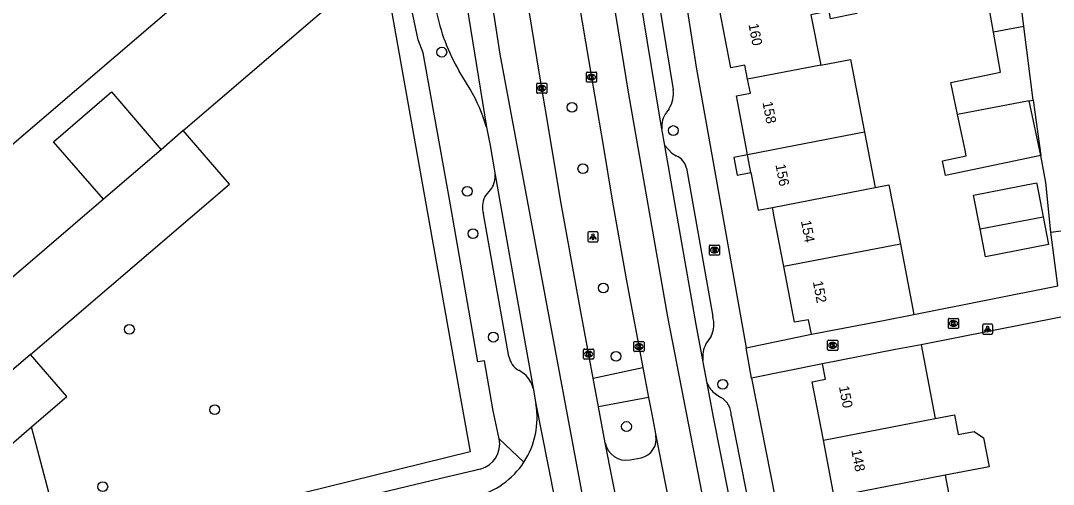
# Model space of a CAD drawing. Extents: x 158474 to 159560, y 388525 to 389605.
# Drawn here: x 159182.5 to 159285.1, y 388966.4 to 389012.4 of the extents above; entities that cross this region are included whole.
import ezdxf

# ---------------------------------------------------------------- set-up
doc = ezdxf.new("R2010")
doc.units = 0
for name, color, linetype in [('IMGEO_Boom', 7, 'Continuous'), ('IMGEO_Brandkraan', 7, 'Continuous'), ('IMGEO_Groenvoorziening', 7, 'Continuous'), ('IMGEO_Kolk', 7, 'Continuous'), ('IMGEO_Lichtpunt', 7, 'Continuous'), ('IMGEO_Muur', 7, 'Continuous'), ('IMGEO_Pand', 7, 'Continuous'), ('IMGEO_Pand_nummerreeks', 7, 'Continuous'), ('IMGEO_Parkeervlak_open', 7, 'Continuous'), ('IMGEO_Rijbaan_lokaal_gesloten', 7, 'Continuous'), ('IMGEO_Rijbaan_lokaal_open', 7, 'Continuous'), ('IMGEO_Voetpad_open', 7, 'Continuous')]:
    doc.layers.add(name, color=color, linetype=linetype)

msp = doc.modelspace()

# ---------------------------------------------------------------- linework, layer by layer
at = {"layer": 'IMGEO_Boom'}
for centre in [(159224.35, 389009.27), (159237.29, 389003.8), (159247.35, 389001.49), (159238.37, 388997.71), (159226.88, 388995.46), (159227.45, 388991.26), (159240.4, 388985.87), (159193.33, 388981.76), (159229.47, 388980.99), (159241.66, 388979.09), (159252.26, 388976.31), (159201.8, 388973.79), (159242.7, 388972.12), (159190.68, 388966.15)]:
    msp.add_circle(centre, 0.489, dxfattribs=at)
at = {"layer": 'IMGEO_Brandkraan'}
for p, q in [((159250.94, 388989.2), (159250.94, 388990.05)), ((159251.01, 388990.13), (159251.87, 388990.13)), ((159251.87, 388989.13), (159251.01, 388989.13)), ((159251.45, 388989.35), (159251.42, 388989.35)), ((159251.43, 388989.91), (159251.45, 388989.91)), ((159251.94, 388990.05), (159251.94, 388989.2))]:
    msp.add_line(p, q, dxfattribs=at)
for points in [[(159250.94, 388989.2), (159250.94, 388990.05)], [(159251.01, 388990.13), (159251.87, 388990.13)], [(159251.87, 388989.13), (159251.01, 388989.13)], [(159251.29, 388989.83), (159251.29, 388989.43), (159251.5, 388989.43)], [(159251.52, 388989.83), (159251.29, 388989.83)], [(159251.46, 388989.75), (159251.41, 388989.75), (159251.41, 388989.67)], [(159251.41, 388989.67), (159251.46, 388989.67)], [(159251.47, 388989.59), (159251.41, 388989.59), (159251.41, 388989.51)], [(159251.41, 388989.51), (159251.47, 388989.51)], [(159251.94, 388990.05), (159251.94, 388989.2)]]:
    msp.add_lwpolyline(points, dxfattribs=at)
for centre, radius, start, end in [((159251.01, 388990.05), 0.0765, 91.552, 178.448), ((159251.01, 388990.05), 0.0765, 91.552, 178.448), ((159251.01, 388989.2), 0.0765, 181.552, 268.448), ((159251.01, 388989.2), 0.0765, 181.552, 268.448), ((159251.47, 388989.71), 0.0379, 267.8285, 90.9355), ((159251.47, 388989.55), 0.0404, 269.8759, 90.5077), ((159251.5, 388989.68), 0.251, 268.6676, 293.5347), ((159251.52, 388989.68), 0.145, 59.4692, 91.5367), ((159251.55, 388989.73), 0.0922, 285.5137, 58.1501), ((159251.55, 388989.54), 0.105, 301.3115, 78.989), ((159251.86, 388990.05), 0.0765, 1.552, 88.448), ((159251.86, 388990.05), 0.0765, 1.552, 88.448), ((159251.86, 388989.2), 0.0765, 271.552, 358.448), ((159251.86, 388989.2), 0.0765, 271.552, 358.448)]:
    msp.add_arc(centre, radius, start, end, dxfattribs=at)
for centre, major_axis, ratio, start_param, end_param in [((159251.43, 388989.63), (-0.387, 0.002), 0.722429, 4.712389, 7.853982), ((159251.45, 388989.63), (-0.39, 0.002), 0.717154, 1.570796, 4.712389)]:
    msp.add_ellipse(centre, major_axis=major_axis, ratio=ratio, start_param=start_param, end_param=end_param, dxfattribs=at)
at = {"layer": 'IMGEO_Groenvoorziening'}
msp.add_lwpolyline([(159218.48, 389018.41), (159226.05, 388975.87), (159227.16, 388969.61), (159186.89, 388959.67), (159183.61, 388972.1)], dxfattribs=at)
at = {"layer": 'IMGEO_Kolk'}
for p, q in [((159238.72, 389006.37), (159238.72, 389007.22)), ((159238.8, 389007.29), (159239.65, 389007.29)), ((159239.21, 389007.07), (159239.24, 389007.07)), ((159239.72, 389007.22), (159239.72, 389006.37)), ((159233.78, 389005.27), (159233.78, 389006.12)), ((159233.85, 389006.19), (159234.71, 389006.19)), ((159234.27, 389005.97), (159234.29, 389005.97)), ((159234.78, 389006.12), (159234.78, 389005.27)), ((159239.65, 389006.29), (159238.8, 389006.29)), ((159239.23, 389006.51), (159239.21, 389006.51)), ((159234.71, 389005.19), (159233.85, 389005.19)), ((159234.29, 389005.41), (159234.27, 389005.41)), ((159274.68, 388981.93), (159274.68, 388982.78)), ((159274.75, 388982.85), (159275.6, 388982.85)), ((159275.16, 388982.63), (159275.19, 388982.63)), ((159275.19, 388982.07), (159275.16, 388982.07)), ((159275.68, 388982.78), (159275.68, 388981.93)), ((159275.6, 388981.85), (159274.75, 388981.85)), ((159243.44, 388979.63), (159243.44, 388980.48)), ((159243.51, 388980.55), (159244.36, 388980.55)), ((159243.92, 388980.33), (159243.95, 388980.33)), ((159244.44, 388980.48), (159244.44, 388979.63)), ((159262.68, 388979.76), (159262.68, 388980.61)), ((159262.76, 388980.69), (159263.61, 388980.69)), ((159263.17, 388980.46), (159263.2, 388980.46)), ((159263.19, 388979.91), (159263.17, 388979.91)), ((159263.68, 388980.61), (159263.68, 388979.76)), ((159238.44, 388978.89), (159238.44, 388979.74)), ((159238.51, 388979.81), (159239.37, 388979.81)), ((159238.93, 388979.59), (159238.95, 388979.59)), ((159238.95, 388979.03), (159238.93, 388979.03)), ((159239.44, 388979.74), (159239.44, 388978.89)), ((159244.36, 388979.55), (159243.51, 388979.55)), ((159243.95, 388979.77), (159243.92, 388979.77)), ((159263.61, 388979.68), (159262.76, 388979.68)), ((159239.37, 388978.81), (159238.51, 388978.81))]:
    msp.add_line(p, q, dxfattribs=at)
for points in [[(159238.72, 389006.37), (159238.72, 389007.22)], [(159238.8, 389007.29), (159239.65, 389007.29)], [(159239.04, 389006.99), (159239.17, 389006.99), (159239.17, 389006.84), (159239.3, 389006.99), (159239.46, 389006.99), (159239.32, 389006.84), (159239.47, 389006.59), (159239.32, 389006.59), (159239.23, 389006.76), (159239.17, 389006.69), (159239.17, 389006.59), (159239.04, 389006.59), (159239.04, 389006.99)], [(159239.72, 389007.22), (159239.72, 389006.37)], [(159233.78, 389005.27), (159233.78, 389006.12)], [(159233.85, 389006.19), (159234.71, 389006.19)], [(159234.1, 389005.89), (159234.22, 389005.89), (159234.22, 389005.74), (159234.35, 389005.89), (159234.52, 389005.89), (159234.37, 389005.74), (159234.52, 389005.49), (159234.37, 389005.49), (159234.29, 389005.66), (159234.22, 389005.59), (159234.22, 389005.49), (159234.1, 389005.49), (159234.1, 389005.89)], [(159234.78, 389006.12), (159234.78, 389005.27)], [(159239.65, 389006.29), (159238.8, 389006.29)], [(159234.71, 389005.19), (159233.85, 389005.19)], [(159274.68, 388981.93), (159274.68, 388982.78)], [(159274.75, 388982.85), (159275.6, 388982.85)], [(159275, 388982.55), (159275.12, 388982.55), (159275.12, 388982.4), (159275.25, 388982.55), (159275.41, 388982.55), (159275.27, 388982.4), (159275.42, 388982.15), (159275.27, 388982.15), (159275.18, 388982.32), (159275.12, 388982.25), (159275.12, 388982.15), (159275, 388982.15), (159275, 388982.55)], [(159275.68, 388982.78), (159275.68, 388981.93)], [(159275.6, 388981.85), (159274.75, 388981.85)], [(159243.44, 388979.63), (159243.44, 388980.48)], [(159243.51, 388980.55), (159244.36, 388980.55)], [(159243.76, 388980.25), (159243.88, 388980.25), (159243.88, 388980.1), (159244.01, 388980.25), (159244.17, 388980.25), (159244.03, 388980.1), (159244.18, 388979.85), (159244.03, 388979.85), (159243.94, 388980.02), (159243.88, 388979.95), (159243.88, 388979.85), (159243.76, 388979.85), (159243.76, 388980.25)], [(159244.44, 388980.48), (159244.44, 388979.63)], [(159262.68, 388979.76), (159262.68, 388980.61)], [(159262.76, 388980.69), (159263.61, 388980.69)], [(159263, 388980.38), (159263.13, 388980.38), (159263.13, 388980.23), (159263.26, 388980.38), (159263.42, 388980.38), (159263.27, 388980.23), (159263.43, 388979.98), (159263.27, 388979.98), (159263.19, 388980.15), (159263.13, 388980.08), (159263.13, 388979.98), (159263, 388979.98), (159263, 388980.38)], [(159263.68, 388980.61), (159263.68, 388979.76)], [(159238.44, 388978.89), (159238.44, 388979.74)], [(159238.51, 388979.81), (159239.37, 388979.81)], [(159238.76, 388979.51), (159238.88, 388979.51), (159238.88, 388979.36), (159239.01, 388979.51), (159239.18, 388979.51), (159239.03, 388979.36), (159239.18, 388979.11), (159239.03, 388979.11), (159238.95, 388979.28), (159238.88, 388979.21), (159238.88, 388979.11), (159238.76, 388979.11), (159238.76, 388979.51)], [(159239.44, 388979.74), (159239.44, 388978.89)], [(159244.36, 388979.55), (159243.51, 388979.55)], [(159263.61, 388979.68), (159262.76, 388979.68)], [(159239.37, 388978.81), (159238.51, 388978.81)]]:
    msp.add_lwpolyline(points, dxfattribs=at)
for centre, start, end in [((159238.8, 389007.22), 91.552, 178.448), ((159238.8, 389007.22), 91.552, 178.448), ((159239.65, 389007.22), 1.552, 88.448), ((159239.65, 389007.22), 1.552, 88.448), ((159233.86, 389006.12), 91.552, 178.448), ((159233.86, 389006.12), 91.552, 178.448), ((159234.7, 389006.12), 1.552, 88.448), ((159234.7, 389006.12), 1.552, 88.448), ((159238.8, 389006.37), 181.552, 268.448), ((159238.8, 389006.37), 181.552, 268.448), ((159239.65, 389006.37), 271.552, 358.448), ((159239.65, 389006.37), 271.552, 358.448), ((159233.86, 389005.27), 181.552, 268.448), ((159233.86, 389005.27), 181.552, 268.448), ((159234.7, 389005.27), 271.552, 358.448), ((159234.7, 389005.27), 271.552, 358.448), ((159274.75, 388982.78), 91.552, 178.448), ((159274.75, 388982.78), 91.552, 178.448), ((159275.6, 388982.78), 1.552, 88.448), ((159275.6, 388982.78), 1.552, 88.448), ((159274.75, 388981.93), 181.552, 268.448), ((159274.75, 388981.93), 181.552, 268.448), ((159275.6, 388981.93), 271.552, 358.448), ((159275.6, 388981.93), 271.552, 358.448), ((159243.51, 388980.48), 91.552, 178.448), ((159243.51, 388980.48), 91.552, 178.448), ((159244.36, 388980.48), 1.552, 88.448), ((159244.36, 388980.48), 1.552, 88.448), ((159262.76, 388980.61), 91.552, 178.448), ((159262.76, 388980.61), 91.552, 178.448), ((159263.61, 388980.61), 1.552, 88.448), ((159263.61, 388980.61), 1.552, 88.448), ((159238.52, 388979.74), 91.552, 178.448), ((159238.52, 388979.74), 91.552, 178.448), ((159238.52, 388978.89), 181.552, 268.448), ((159238.52, 388978.89), 181.552, 268.448), ((159239.36, 388979.74), 1.552, 88.448), ((159239.36, 388979.74), 1.552, 88.448), ((159239.36, 388978.89), 271.552, 358.448), ((159239.36, 388978.89), 271.552, 358.448), ((159243.51, 388979.63), 181.552, 268.448), ((159243.51, 388979.63), 181.552, 268.448), ((159244.36, 388979.63), 271.552, 358.448), ((159244.36, 388979.63), 271.552, 358.448), ((159262.76, 388979.76), 181.552, 268.448), ((159262.76, 388979.76), 181.552, 268.448), ((159263.61, 388979.76), 271.552, 358.448), ((159263.61, 388979.76), 271.552, 358.448)]:
    msp.add_arc(centre, 0.0765, start, end, dxfattribs=at)
for centre, major_axis, ratio, start_param, end_param in [((159239.21, 389006.79), (-0.387, 0.002), 0.722429, 4.712389, 7.853982), ((159239.23, 389006.79), (-0.39, 0.002), 0.717154, 1.570796, 4.712389), ((159234.27, 389005.69), (-0.387, 0.002), 0.722429, 4.712389, 7.853982), ((159234.29, 389005.69), (-0.39, 0.002), 0.717154, 1.570796, 4.712389), ((159275.16, 388982.35), (-0.387, 0.002), 0.722429, 4.712389, 7.853982), ((159275.19, 388982.35), (-0.39, 0.002), 0.717154, 1.570796, 4.712389), ((159243.92, 388980.05), (-0.387, 0.002), 0.722429, 4.712389, 7.853982), ((159243.95, 388980.05), (-0.39, 0.002), 0.717154, 1.570796, 4.712389), ((159263.17, 388980.18), (-0.387, 0.002), 0.722429, 4.712389, 7.853982), ((159263.19, 388980.18), (-0.39, 0.002), 0.717154, 1.570796, 4.712389), ((159238.93, 388979.31), (-0.387, 0.002), 0.722429, 4.712389, 7.853982), ((159238.95, 388979.31), (-0.39, 0.002), 0.717154, 1.570796, 4.712389)]:
    msp.add_ellipse(centre, major_axis=major_axis, ratio=ratio, start_param=start_param, end_param=end_param, dxfattribs=at)
at = {"layer": 'IMGEO_Lichtpunt'}
for p, q in [((159238.87, 388991.34), (159238.87, 388990.54)), ((159238.87, 388991.34), (159238.87, 388990.54)), ((159239.77, 388991.44), (159238.97, 388991.44)), ((159239.77, 388991.44), (159238.97, 388991.44)), ((159239.87, 388990.54), (159239.87, 388991.34)), ((159239.87, 388990.54), (159239.87, 388991.34)), ((159238.97, 388990.44), (159239.77, 388990.44)), ((159238.97, 388990.44), (159239.77, 388990.44)), ((159278.07, 388982.19), (159278.07, 388981.38)), ((159278.07, 388982.19), (159278.07, 388981.38)), ((159278.97, 388982.28), (159278.17, 388982.28)), ((159278.97, 388982.28), (159278.17, 388982.28)), ((159279.07, 388981.38), (159279.07, 388982.19)), ((159279.07, 388981.38), (159279.07, 388982.19)), ((159278.17, 388981.29), (159278.97, 388981.29)), ((159278.17, 388981.29), (159278.97, 388981.29))]:
    msp.add_line(p, q, dxfattribs=at)
for points in [[(159239.25, 388991.01), (159239.29, 388990.98), (159239.1, 388990.72), (159239.06, 388990.74), (159239.25, 388991.01)], [(159239.35, 388990.96), (159239.4, 388990.96), (159239.4, 388990.64), (159239.35, 388990.64), (159239.35, 388990.96)], [(159239.46, 388990.98), (159239.5, 388991.01), (159239.68, 388990.74), (159239.65, 388990.72), (159239.46, 388990.98)], [(159278.45, 388981.85), (159278.49, 388981.82), (159278.3, 388981.56), (159278.26, 388981.59), (159278.45, 388981.85)], [(159278.55, 388981.8), (159278.6, 388981.8), (159278.6, 388981.48), (159278.55, 388981.48), (159278.55, 388981.8)], [(159278.66, 388981.82), (159278.7, 388981.85), (159278.88, 388981.59), (159278.85, 388981.56), (159278.66, 388981.82)]]:
    msp.add_lwpolyline(points, dxfattribs=at)
for centre in [(159239.37, 388991.14), (159278.57, 388981.99)]:
    msp.add_circle(centre, 0.0994, dxfattribs=at)
for centre, start, end in [((159238.97, 388991.34), 90, 180), ((159238.97, 388991.34), 90, 180), ((159239.77, 388991.34), 0, 90), ((159239.77, 388991.34), 0, 90), ((159238.97, 388990.54), 180, 270), ((159238.97, 388990.54), 180, 270), ((159239.77, 388990.54), 270, 0), ((159239.77, 388990.54), 270, 360), ((159278.17, 388982.19), 90, 180), ((159278.17, 388982.19), 90, 180), ((159278.97, 388982.19), 0, 90), ((159278.97, 388982.19), 0, 90), ((159278.17, 388981.38), 180, 270), ((159278.17, 388981.38), 180, 270), ((159278.97, 388981.38), 270, 0), ((159278.97, 388981.38), 270, 360)]:
    msp.add_arc(centre, 0.0946, start, end, dxfattribs=at)
at = {"layer": 'IMGEO_Muur'}
msp.add_lwpolyline([(159284.35, 388996.32), (159283.85, 388999.02)], dxfattribs=at)
at = {"layer": 'IMGEO_Pand'}
for points in [[(159193.12, 389029.9), (159203.02, 389018.34), (159177.24, 388996.29), (159165.48, 388986.23), (159155.42, 388997.94)], [(159263.06, 389015.68), (159264.16, 389015.89), (159264.25, 389015.4), (159265.09, 389015.56), (159265.57, 389013.09), (159262.96, 389012.58), (159262.82, 389013.33), (159261.02, 389012.98), (159261.99, 389007.97)], [(159282.17, 389011.83), (159281.63, 389016.18), (159279.64, 389015.78)], [(159279.15, 389011.25), (159278.4, 389015.54)], [(159254.73, 389006.59), (159254.46, 389007.99), (159253.05, 389007.72), (159251.93, 389013.52)], [(159282.17, 389011.83), (159279.15, 389011.25)], [(159283.08, 389004.52), (159282.17, 389011.83)], [(159275.58, 389003.09), (159274.92, 389006.25), (159279.84, 389007.29), (159279.15, 389011.25)], [(159261.99, 389007.97), (159254.73, 389006.59)], [(159261.99, 389007.97), (159264.96, 389008.55), (159266.34, 389001.32)], [(159254.73, 388999.09), (159254.55, 389000), (159253.61, 389004.92), (159255, 389005.19), (159254.73, 389006.59)], [(159282.7, 389004.45), (159283.08, 389004.52)], [(159282.7, 389004.45), (159275.58, 389003.09)], [(159283.85, 388999.02), (159282.7, 389004.45)], [(159283.85, 388999.02), (159274.4, 388997.02), (159274.1, 388998.49), (159276.44, 388998.99), (159276.33, 388999.54), (159276.23, 389000), (159275.58, 389003.09)], [(159266.34, 389001.32), (159259.47, 389000), (159254.73, 388999.09)], [(159266.34, 389001.32), (159267.4, 388995.83)], [(159254.73, 388999.09), (159253.35, 388998.83), (159253.69, 388997.07), (159255.06, 388997.33)], [(159255.06, 388997.33), (159254.73, 388999.09)], [(159255.06, 388997.33), (159255.78, 388993.6), (159257.19, 388993.87)], [(159277.83, 388991.73), (159277.17, 388995.09), (159283.43, 388996.31), (159283.46, 388996.19), (159284.09, 388992.94)], [(159257.19, 388993.87), (159267.4, 388995.83)], [(159267.4, 388995.83), (159268.77, 388996.09), (159269.9, 388990.21)], [(159258.32, 388987.99), (159257.34, 388993.11), (159257.26, 388993.53), (159257.19, 388993.87)], [(159284.09, 388992.94), (159284.63, 388990.17), (159278.37, 388988.95), (159277.83, 388991.73)], [(159277.83, 388991.73), (159284.09, 388992.94)], [(159269.9, 388990.21), (159258.32, 388987.99)], [(159269.9, 388990.21), (159271.23, 388983.25)], [(159261.06, 388981.28), (159260.78, 388982.72), (159259.38, 388982.46), (159258.32, 388987.99)], [(159261.06, 388981.28), (159268.22, 388982.65), (159271.23, 388983.25)], [(159271.96, 388980.24), (159269.42, 388979.75), (159262.18, 388978.35)], [(159271.96, 388980.24), (159273.37, 388972.93)], [(159262.25, 388970.78), (159261.13, 388976.55), (159262.48, 388976.81), (159262.18, 388978.35)], [(159262.25, 388970.78), (159273.37, 388972.93)], [(159273.37, 388972.93), (159275.27, 388973.29), (159275.65, 388971.33), (159277.22, 388971.64), (159278.17, 388970.99), (159278.72, 388968.13), (159274.34, 388967.29)], [(159263.33, 388965.16), (159262.25, 388970.78)], [(159274.34, 388967.29), (159263.33, 388965.16)], [(159274.34, 388967.29), (159274.81, 388964.85), (159275.73, 388960.14)]]:
    msp.add_lwpolyline(points, dxfattribs=at)
at = {"layer": 'IMGEO_Parkeervlak_open'}
for points in [[(159183.61, 388972.1), (159187.11, 388975.11), (159183.5, 388979.26)], [(159173.58, 388963.44), (159183.61, 388972.1)]]:
    msp.add_lwpolyline(points, dxfattribs=at)
at = {"layer": 'IMGEO_Rijbaan_lokaal_gesloten'}
for points in [[(159268.08, 388832.36), (159258.63, 388872.24), (159243.1, 388939.79), (159230.16, 389009.07), (159223.47, 389052.45)], [(159221.3, 389051.06), (159225.26, 389023.69), (159228.79, 389001.83)], [(159235.99, 389049.75), (159239.31, 389027.03), (159242.91, 389005.1), (159246.77, 388983.01), (159252.03, 388955.95), (159255.77, 388938.11), (159261.43, 388912.54), (159265.14, 388896.85), (159270.67, 388873.44), (159274.33, 388857.95), (159279.71, 388835.25)], [(159239.38, 388976.92), (159238.1, 388983.85), (159236.16, 388994.61), (159235.24, 389000), (159234.01, 389007.3), (159232.29, 389017.88), (159230.39, 389029.83), (159228.92, 389039.21), (159228.11, 389045.6)], [(159233.05, 389046.25), (159234.72, 389034.81), (159235.87, 389027.24), (159237.37, 389017.74), (159239.56, 389004.84), (159240.37, 389000), (159241.28, 388994.58), (159242.71, 388986.57), (159244.33, 388977.97)], [(159246.22, 389001.67), (159245.95, 389003.2), (159244.03, 389014.91), (159243.35, 389019.24)], [(159228.79, 389001.83), (159228.96, 389001.01), (159229.15, 389000), (159229.66, 388997.11)], [(159246.51, 389000), (159246.22, 389001.67)], [(159250.29, 388978.69), (159249.63, 388982.26), (159247.62, 388993.55), (159246.51, 389000)], [(159229.66, 388997.11), (159231.58, 388986.25), (159233.42, 388975.92)], [(159244.33, 388977.97), (159244.89, 388975)], [(159250.72, 388976.41), (159250.33, 388978.52), (159250.29, 388978.69)], [(159239.91, 388974.09), (159239.38, 388976.92)], [(159233.42, 388975.92), (159233.69, 388974.37)], [(159255.47, 388952.3), (159253.58, 388961.7), (159251.34, 388973.04), (159250.72, 388976.41)], [(159244.89, 388975), (159245.2, 388973.35), (159245.61, 388971.24)], [(159233.69, 388974.37), (159238.04, 388952.46)], [(159240.58, 388970.49), (159239.91, 388974.09)], [(159245.61, 388971.24), (159247.8, 388960.07)], [(159242.84, 388959.15), (159240.58, 388970.49)]]:
    msp.add_lwpolyline(points, dxfattribs=at)
at = {"layer": 'IMGEO_Rijbaan_lokaal_open'}
for points in [[(159227.17, 389005.6), (159226.09, 389007.38)], [(159283.08, 389004.52), (159283.85, 388999.02)], [(159183.5, 388979.26), (159203.26, 388996.16), (159198.68, 389001.48)], [(159198.68, 389001.48), (159196.48, 388999.59)], [(159196.48, 388999.59), (159190.74, 388994.67)], [(159284.85, 388991.4), (159284.35, 388996.32), (159283.85, 388999.02)], [(159190.74, 388994.67), (159170.1, 388976.99)], [(159284.85, 388991.4), (159290.93, 388992.2)], [(159183.5, 388979.26), (159172.15, 388969.53)], [(159243.06, 388968.8), (159244.14, 388969.01)]]:
    msp.add_lwpolyline(points, dxfattribs=at)
for centre, radius, start, end in [((159242.47, 389017.05), 19.02, 190.8494, 210.5715), ((159212.75, 388997.15), 16.71, 16.2771, 30.3769), ((159225.83, 388972.97), 7.99, 326.7297, 10.0987), ((159243.71, 388970.9), 1.94, 282.9368, 10.1592), ((159242.7, 388970.95), 2.18, 192.1086, 279.4751), ((159225.82, 388972.97), 8, 283.3917, 326.7386)]:
    msp.add_arc(centre, radius, start, end, dxfattribs=at)
at = {"layer": 'IMGEO_Voetpad_open'}
for points in [[(159242.55, 389053.11), (159249.64, 389007.58), (159251, 389000), (159254.6, 388979.92)], [(159230.06, 388970.9), (159229.47, 388973.69), (159228.61, 388978.65), (159227.94, 388978.55), (159225.22, 388994.12), (159224.16, 389000), (159222.5, 389009.21), (159222.01, 389010.48), (159221.04, 389015.05), (159220.23, 389019.91)], [(159198.68, 389001.48), (159211.76, 389012.66), (159218.48, 389018.41)], [(159245.57, 389016.27), (159247.33, 389005.56)], [(159190.74, 388994.67), (159185.79, 389000.38), (159191.54, 389005.32), (159196.48, 388999.59)], [(159246.93, 389003.66), (159246.68, 389003.3)], [(159246.51, 389000), (159247.19, 388999.25), (159247.63, 388998.97)], [(159248.67, 388997.77), (159251.27, 388983.04)], [(159228.63, 388994.9), (159229.31, 388995.76)], [(159231.02, 388979.07), (159228.51, 388993.24)], [(159271.23, 388983.25), (159285.53, 388986.08), (159284.85, 388991.4)], [(159292.85, 388984.37), (159271.96, 388980.24)], [(159251.1, 388981.08), (159250.59, 388980.31)], [(159254.6, 388979.92), (159261.06, 388981.28)], [(159255.12, 388976.93), (159254.6, 388979.92)], [(159239.38, 388976.92), (159244.33, 388977.97)], [(159262.18, 388978.35), (159255.12, 388976.93)], [(159232.57, 388977.31), (159231.99, 388977.7)], [(159255.12, 388976.93), (159260.32, 388950.6), (159261.47, 388949.73), (159262.87, 388943.36)], [(159244.89, 388975), (159239.91, 388974.09)], [(159251.55, 388975.36), (159252.07, 388975.01)], [(159253.09, 388973.21), (159256.42, 388956.44)], [(159232.51, 388968.59), (159230.06, 388970.9)], [(159228.18, 388967.9), (159228.01, 388967.86), (159227.5, 388967.74), (159224.83, 388967.1), (159178.64, 388956.05)]]:
    msp.add_lwpolyline(points, dxfattribs=at)
for centre, radius, start, end in [((159244.73, 389005.12), 2.63, 326.5596, 9.7544), ((159248.36, 389001.93), 2.16, 140.8184, 187.1423), ((159247.02, 388997.39), 1.69, 13.0088, 69.0165), ((159227.43, 388996.97), 2.23, 327.3555, 3.7142), ((159230.49, 388993.93), 2.1, 152.5534, 199.246), ((159248.77, 388982.26), 2.61, 333.0421, 17.498), ((159252.9, 388979.05), 2.63, 151.3386, 187.9087), ((159232.97, 388979.42), 1.98, 190.1167, 240.2758), ((159230.99, 388975.39), 2.49, 12.5148, 50.6355), ((159252.6, 388977.05), 1.98, 198.7182, 238.2011), ((159251.18, 388973.31), 1.91, 356.9478, 62.4666), ((159227.51, 388970.41), 2.6, 284.9068, 10.8113)]:
    msp.add_arc(centre, radius, start, end, dxfattribs=at)

# ---------------------------------------------------------------- texts
at = {"layer": 'IMGEO_Pand_nummerreeks'}
for s, rotation, p in [('160', 280.8681, (159254.81, 389012.03)), ('158', 280.8681, (159256.2, 389004.29)), ('156', 280.8631, (159257.49, 388998.09)), ('154', 280.8688, (159260.02, 388992.5)), ('152', 280.8684, (159261.2, 388986.49)), ('150', 280.9379, (159263.79, 388976.07)), ('148', 280.9379, (159265.02, 388969.76))]:
    msp.add_text(s, height=1, rotation=rotation, dxfattribs=at).set_placement(p)

doc.saveas('drawing.dxf')
